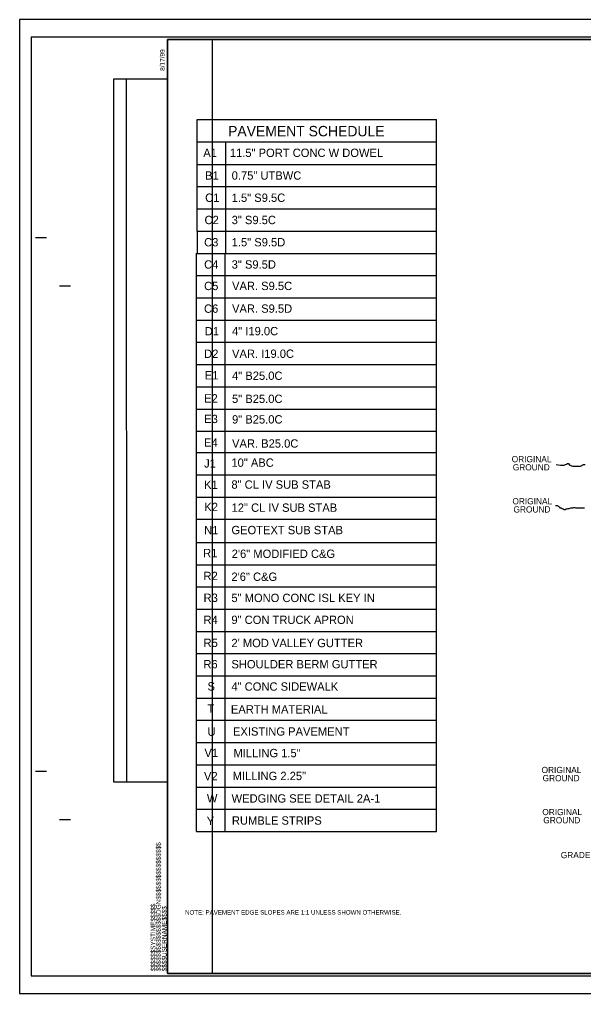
# Model space of a CAD drawing. Extents: x 1640342 to 1730599, y 538663 to 843747.
# Drawn here: x 1729840.7 to 1729967.5, y 539149.8 to 539368.8 of the extents above; entities that cross this region are included whole.
import ezdxf

# ---------------------------------------------------------------- set-up
doc = ezdxf.new("R2010")
doc.units = 0
for name, color, linetype in [('Default', 7, 'Continuous'), ('Old_Level_19', 7, 'Continuous'), ('Old_Level_21', 7, 'Continuous'), ('Sheet Block Revision CELL', 7, 'Continuous'), ('Sheet Clip Boundary CELL', 7, 'Continuous'), ('Sheet Layout Plan Border', 7, 'Continuous'), ('Sheet Plan CELL', 7, 'Continuous'), ('Sheet Plan Layout CELL', 7, 'Continuous'), ('Sheet Plot Border Inside CELL', 7, 'Continuous'), ('Sheet Plot Border Outside CELL', 7, 'Continuous'), ('Typical Hinge Slope Arterial CELL', 7, 'Continuous'), ('Typical Hinge Slope Interstate CELL', 7, 'Continuous'), ('Typical Text General CELL', 7, 'Continuous')]:
    doc.layers.add(name, color=color, linetype=linetype)

msp = doc.modelspace()

# ---------------------------------------------------------------- linework, layer by layer
at = {"layer": 'Old_Level_19'}
for p, q in [((1729880.62, 539346.28), (1729934.5, 539346.28)), ((1729880.62, 539341.28), (1729880.62, 539346.28)), ((1729934.5, 539186.2), (1729934.5, 539346.28)), ((1729880.62, 539336.19), (1729880.62, 539341.28)), ((1729880.62, 539341.28), (1729934.5, 539341.28)), ((1729887.11, 539336.19), (1729887.11, 539341.28)), ((1729880.62, 539331.19), (1729880.62, 539336.19)), ((1729880.62, 539336.19), (1729934.5, 539336.19)), ((1729887.11, 539331.19), (1729887.11, 539336.19)), ((1729880.62, 539331.19), (1729934.5, 539331.19)), ((1729880.62, 539326.19), (1729880.62, 539331.19)), ((1729887.11, 539326.19), (1729887.11, 539331.19)), ((1729880.62, 539326.19), (1729934.5, 539326.19)), ((1729880.62, 539321.19), (1729880.62, 539326.19)), ((1729887.11, 539321.19), (1729887.11, 539326.19)), ((1729880.62, 539321.19), (1729880.62, 539316.19)), ((1729880.62, 539321.19), (1729934.5, 539321.19)), ((1729887.11, 539316.19), (1729887.11, 539321.19)), ((1729880.48, 539186.2), (1729880.48, 539316.2)), ((1729880.62, 539316.19), (1729920.63, 539316.19)), ((1729880.62, 539316.19), (1729934.5, 539316.19)), ((1729886.98, 539186.2), (1729886.98, 539316.2)), ((1729880.62, 539311.19), (1729934.5, 539311.19)), ((1729880.62, 539306.19), (1729934.5, 539306.19)), ((1729880.62, 539301.19), (1729934.5, 539301.19)), ((1729880.62, 539296.19), (1729934.5, 539296.19)), ((1729880.62, 539291.19), (1729934.5, 539291.19)), ((1729880.62, 539286.19), (1729934.5, 539286.19)), ((1729880.62, 539281.19), (1729934.5, 539281.19)), ((1729880.62, 539276.19), (1729934.5, 539276.19)), ((1729880.48, 539271.41), (1729934.5, 539271.41)), ((1729880.48, 539266.41), (1729934.5, 539266.41)), ((1729880.48, 539261.41), (1729934.5, 539261.41)), ((1729880.48, 539256.41), (1729934.5, 539256.41)), ((1729880.48, 539251.2), (1729934.5, 539251.2)), ((1729880.48, 539246.19), (1729934.5, 539246.19)), ((1729880.48, 539241.2), (1729934.5, 539241.2)), ((1729880.48, 539236.2), (1729934.5, 539236.2)), ((1729880.48, 539231.2), (1729934.5, 539231.2)), ((1729880.48, 539226.2), (1729934.5, 539226.2)), ((1729880.48, 539221.2), (1729934.5, 539221.2)), ((1729880.48, 539216.2), (1729934.5, 539216.2)), ((1729880.48, 539211.2), (1729934.5, 539211.2)), ((1729880.48, 539206.2), (1729934.5, 539206.2)), ((1729880.48, 539201.2), (1729934.5, 539201.2)), ((1729880.48, 539196.2), (1729934.5, 539196.2)), ((1729880.48, 539191.2), (1729934.5, 539191.2)), ((1729880.48, 539186.2), (1729934.5, 539186.2))]:
    msp.add_line(p, q, dxfattribs=at)
at = {"layer": 'Sheet Block Revision CELL'}
msp.add_line((1729864.8, 539197.28), (1729864.79, 539355.41), dxfattribs=at)
msp.add_lwpolyline([(1729861.89, 539197.27), (1729861.89, 539355.4), (1729873.99, 539355.41), (1729873.99, 539197.28)], close=True, dxfattribs=at)
at = {"layer": 'Sheet Clip Boundary CELL'}
msp.add_lwpolyline([(1729883.99, 539154.28), (1730163.99, 539154.28), (1730163.99, 539321.98), (1730126.14, 539321.98), (1730126.14, 539364.28), (1729883.99, 539364.28)], close=True, dxfattribs=at)
at = {"layer": 'Sheet Layout Plan Border'}
msp.add_lwpolyline([(1729883.99, 539154.28), (1730163.99, 539154.28), (1730163.99, 539321.98), (1730126.14, 539321.98), (1730126.14, 539364.28), (1729883.99, 539364.28)], close=True, dxfattribs=at)
at = {"layer": 'Sheet Plan CELL'}
for p, q in [((1729873.99, 539364.28), (1729873.99, 539364.28)), ((1729844.29, 539319.77), (1729846.79, 539319.78)), ((1729849.69, 539308.87), (1729852.2, 539308.87)), ((1729844.3, 539199.78), (1729846.8, 539199.77)), ((1729849.7, 539188.87), (1729852.2, 539188.87)), ((1729873.99, 539154.28), (1729873.99, 539154.28))]:
    msp.add_line(p, q, dxfattribs=at)
for points in [[(1730174, 539364.28), (1729873.99, 539364.28), (1729873.99, 539154.28), (1730173.99, 539154.28)], [(1729873.99, 539154.28), (1729873.99, 539364.27), (1730133.98, 539364.28), (1730133.99, 539334.27), (1730173.99, 539334.27), (1730173.99, 539154.28)]]:
    msp.add_lwpolyline(points, close=True, dxfattribs=at)
at = {"layer": 'Sheet Plan Layout CELL'}
msp.add_lwpolyline([(1729873.99, 539364.27), (1729873.99, 539154.28), (1730173.99, 539154.28), (1730173.99, 539321.98), (1730126.14, 539321.98), (1730126.14, 539364.28)], close=True, dxfattribs=at)
at = {"layer": 'Sheet Plot Border Inside CELL'}
msp.add_lwpolyline([(1729843.29, 539153.78), (1730176.49, 539153.78), (1730176.49, 539364.78), (1729843.29, 539364.78)], close=True, dxfattribs=at)
at = {"layer": 'Sheet Plot Border Outside CELL'}
msp.add_lwpolyline([(1729840.69, 539149.78), (1730177.39, 539149.78), (1730177.39, 539368.78), (1729840.69, 539368.78)], close=True, dxfattribs=at)
at = {"layer": 'Typical Hinge Slope Arterial CELL'}
msp.add_lwpolyline([(1729961.35, 539268.69), (1729962.33, 539268.56), (1729962.58, 539268.56), (1729962.95, 539268.56), (1729963.19, 539268.56), (1729963.44, 539268.69), (1729963.68, 539268.81), (1729963.93, 539268.93), (1729964.18, 539268.93), (1729964.3, 539268.69), (1729964.55, 539268.56), (1729964.79, 539268.44), (1729965.04, 539268.32), (1729965.29, 539268.32), (1729965.53, 539268.32), (1729965.78, 539268.32), (1729966.02, 539268.32), (1729966.27, 539268.32), (1729966.52, 539268.32), (1729966.76, 539268.32), (1729967.01, 539268.44), (1729967.25, 539268.56), (1729967.5, 539268.69), (1729967.87, 539268.69)], dxfattribs=at)
at = {"layer": 'Typical Hinge Slope Interstate CELL'}
msp.add_lwpolyline([(1729961.19, 539259.53), (1729961.42, 539259.53), (1729961.65, 539259.53), (1729961.88, 539259.3), (1729962.11, 539259.18), (1729962.23, 539258.95), (1729962.46, 539258.95), (1729962.69, 539258.84), (1729962.92, 539258.72), (1729963.15, 539258.61), (1729963.38, 539258.61), (1729963.61, 539258.72), (1729963.84, 539258.72), (1729964.07, 539258.84), (1729964.3, 539258.84), (1729964.65, 539258.95), (1729964.88, 539258.95), (1729965.11, 539258.95), (1729965.34, 539259.07), (1729965.57, 539259.07), (1729965.8, 539258.95), (1729966.03, 539258.95), (1729966.26, 539258.95), (1729966.49, 539258.95), (1729966.72, 539258.95), (1729967.07, 539258.95), (1729967.41, 539258.95), (1729967.76, 539258.95)], dxfattribs=at)

# ---------------------------------------------------------------- texts
at = {"layer": 'Default'}
for s, height, p in [('ORIGINAL', 1.4, (1729951.37, 539269.23)), ('GROUND', 1.4, (1729951.61, 539267.39)), ('ORIGINAL', 1.4, (1729951.53, 539259.76)), ('GROUND', 1.4, (1729951.77, 539257.92)), ('ORIGINAL', 1.4, (1729958.09, 539199.34)), ('GROUND', 1.4, (1729958.32, 539197.51)), ('ORIGINAL', 1.4, (1729958.25, 539189.88)), ('GROUND', 1.4, (1729958.48, 539188.04)), ('NOTE: PAVEMENT EDGE SLOPES ARE 1:1 UNLESS SHOWN OTHERWISE.', 1, (1729877.93, 539167.52))]:
    msp.add_text(s, height=height, dxfattribs=at).set_placement(p)
at = {"layer": 'Old_Level_21'}
for s, height, p in [('PAVEMENT SCHEDULE', 2.3438, (1729887.6, 539342.5)), ('A1', 1.875, (1729882.02, 539337.86)), ('11.5" PORT CONC W DOWEL', 1.875, (1729888, 539337.86)), ('B1', 1.875, (1729882.44, 539332.76)), ('0.75" UTBWC', 1.875, (1729888.41, 539332.76)), ('C1', 1.875, (1729882.44, 539327.76)), ('1.5" S9.5C', 1.875, (1729888.41, 539327.76)), ('C2', 1.875, (1729882.3, 539322.76)), ('3" S9.5C', 1.875, (1729888.41, 539322.76)), ('C3', 1.875, (1729882.21, 539317.76)), ('1.5" S9.5D', 1.875, (1729888.41, 539317.76)), ('C4', 1.875, (1729882.21, 539312.76)), ('3" S9.5D', 1.875, (1729888.41, 539312.76)), ('C5', 1.875, (1729882.21, 539307.93)), ('VAR. S9.5C', 1.875, (1729888.49, 539307.94)), ('C6', 1.875, (1729882.19, 539302.83)), ('VAR. S9.5D', 1.875, (1729888.49, 539302.84)), ('D1', 1.875, (1729882.35, 539297.75)), ('4" I19.0C', 1.875, (1729888.49, 539297.77)), ('D2', 1.875, (1729882.21, 539292.68)), ('VAR. I19.0C', 1.875, (1729888.49, 539292.69)), ('E1', 1.875, (1729882.35, 539287.84)), ('4" B25.0C', 1.875, (1729888.49, 539287.74)), ('E2', 1.875, (1729882.21, 539282.65)), ('5" B25.0C', 1.875, (1729888.49, 539282.55)), ('E3', 1.875, (1729882.22, 539278.03)), ('9" B25.0C', 1.875, (1729888.49, 539277.93)), ('E4', 1.875, (1729882.2, 539272.73)), ('VAR. B25.0C', 1.875, (1729888.49, 539272.51)), ('10" ABC', 1.875, (1729888.35, 539268.2)), ('J1', 1.875, (1729882.21, 539268.03)), ('K1', 1.875, (1729882.21, 539263.23)), ('8" CL IV SUB STAB', 1.875, (1729888.35, 539263.27)), ('K2', 1.875, (1729882.25, 539258.24)), ('12" CL IV SUB STAB', 1.875, (1729888.39, 539258.08)), ('N1', 1.875, (1729882.21, 539253.01)), ('GEOTEXT SUB STAB', 1.875, (1729888.35, 539253.04)), ('R1', 1.875, (1729881.99, 539247.87)), ('2\'6" MODIFIED C&G', 1.875, (1729888.42, 539247.71)), ('R2', 1.875, (1729882.07, 539242.73)), ('2\'6" C&G', 1.875, (1729888.35, 539242.55)), ('R3', 1.875, (1729882.09, 539237.82)), ('5" MONO CONC ISL KEY IN', 1.875, (1729888.35, 539237.79)), ('R4', 1.875, (1729882.07, 539232.86)), ('9" CON TRUCK APRON', 1.875, (1729888.35, 539232.86)), ('R5', 1.875, (1729882.08, 539227.69)), ("2' MOD VALLEY GUTTER", 1.875, (1729888.35, 539227.65)), ('R6', 1.875, (1729882.05, 539222.89)), ('SHOULDER BERM GUTTER', 1.875, (1729888.35, 539222.88)), ('S', 1.88, (1729882.97, 539217.89)), ('4" CONC SIDEWALK', 1.875, (1729888.35, 539217.86)), ('T', 1.88, (1729882.97, 539212.89)), ('EARTH MATERIAL', 1.875, (1729888.23, 539212.73)), ('U', 1.88, (1729882.97, 539207.71)), ('EXISTING PAVEMENT', 1.875, (1729888.7, 539207.76)), ('V1', 1.875, (1729882.28, 539202.95)), ('MILLING 1.5"', 1.875, (1729888.81, 539202.9)), ('V2', 1.875, (1729882.18, 539197.7)), ('MILLING 2.25"', 1.875, (1729888.63, 539197.76)), ('W', 1.88, (1729882.84, 539192.76)), ('WEDGING SEE DETAIL 2A-1', 1.875, (1729888.39, 539192.7)), ('Y', 1.88, (1729882.8, 539187.63)), ('RUMBLE STRIPS', 1.875, (1729888.46, 539187.74))]:
    msp.add_text(s, height=height, dxfattribs=at).set_placement(p)
at = {"layer": 'Sheet Plan CELL'}
for s, p in [('8/17/99', (1729873.35, 539357.23)), ('$$$$$$$$$$$$$$$$DGN$$$$$$$$$$$$$$$$', (1729872.46, 539154.75)), ('$$$$$$SYSTIME$$$$$', (1729871.25, 539154.75)), ('$$$$USERNAME$$$$', (1729873.77, 539154.75))]:
    msp.add_text(s, height=1.05, rotation=90, dxfattribs=at).set_placement(p)
at = {"layer": 'Typical Text General CELL'}
msp.add_text('GRADE TO THIS LINE', height=1.4, dxfattribs=at).set_placement((1729962.41, 539180.21))

doc.saveas('drawing.dxf')
